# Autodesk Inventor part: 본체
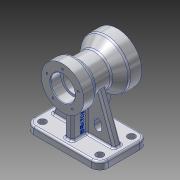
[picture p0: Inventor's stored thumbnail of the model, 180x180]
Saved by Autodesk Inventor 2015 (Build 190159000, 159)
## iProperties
Created: 2015-08
Part Number: 본체
Material: Aluminum 6061
Document SubType Name: Modeling
Designer: 601
Density: 2.7 g/cm^3
Appearance: Aluminum - Flat
Author: 601
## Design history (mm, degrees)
sketch "Sketch3"
  geometry: L1 (20, -5.906)-(20, -22.906); L2 (20, -22.906)-(16, -22.906); L3 (16, -22.906)-(16, -72.906); L4 (0, 0)-(0, -90); L5 (26, -95.906)-(26, -75.906); L6 (35, -5.906)-(35, -25.906); L7 (26, -95.906)-(40, -95.906); L8 (40, -95.906)-(40, -75.906); L9 (26.173, -31.002)-(35, -25.906); L10 (26.173, -59.428)-(40, -75.906); L11 (20, -17.072)-(20, -22.906); L12 (26.173, -31.002)-(26.173, -59.428); L13 (35, -5.906)-(20, -5.906); L14 (26, -75.906)-(19, -75.906); L15 (19, -75.906)-(19, -72.906); L16 (19, -72.906)-(16, -72.906)
  constraints: 32 end point, 7 vertical, 4 horizontal, 3 perpendicular
  dimensions: "d31" = 17 distance of L1.start L1.end; "d32" = 20 distance from line of L4.start L1; "d36" = 90 distance of L4.start L4.end; "d38" = 26 distance between parallel lines of L4 L5; "d39" = 20 distance of L6.start L6.end; "d40" = 35 distance between parallel lines of L4 L6; "d45" = 20 distance of L7.end L8.end; "d46" = 40 distance from line of L4 L7.end; "d132" = 90 distance between parallel lines of L7 L13; "d133" = 60 deg angle of L12 L9; "d134" = 40 deg angle of L12 L10; "d135" = 7 distance of L5.end L14.end; "d138" = 16 distance between parallel lines of L4 L3; "d139" = 50 distance between parallel lines of L2 L16; "d140" = 26.17342 distance between parallel lines of L4 L12
revolve "Revolution2" sketch "Sketch3" stored, may be unused: angle "d50" = 90 deg
workplane "Work Plane2"
sketch "Sketch7"
  geometry: L1 (-47, -85.906)-(47, -85.906); L2 (61, -71.906)-(61, -19.906); L3 (47, -5.906)-(-47, -5.906); L4 (-61, -19.906)-(-61, -71.906); C1 r 6 at (47, -71.906); C2 r 6 at (47, -19.906); C3 r 6 at (-47, -71.906); C4 r 6 at (-47, -19.906); A1 r 14 centre (-47, -19.906) between (-47, -5.906) and (-61, -19.906); A2 r 14 centre (47, -19.906) between (61, -19.906) and (47, -5.906); A3 r 14 centre (47, -71.906) between (47, -85.906) and (61, -71.906); A4 r 14 centre (-47, -71.906) between (-61, -71.906) and (-47, -85.906); 6 further points; 1 other entity
  constraints: 8 centre point, 8 end point, 8 point on circle, 8 tangent, 6 point on line, 5 equal radius, 2 horizontal alignment, 2 parallel, 1 coincident, 1 horizontal, 1 perpendicular, 1 vertical, 3 other
  dimensions: "d76" = 122 distance of point (-61, -5.906) point (61, -5.906); "d77" = 80 distance of point (61, -5.906) point (61, -85.906); "d78" = 80 dimension on L1; "d79" = 61 distance from line of point (0, 0) L4; "d80" = 14 radius of A1; "d81" = 12 diameter of C1; "d84" = 52 distance of C1.centre C2.centre; "d87" = 94 distance of C1.centre C3.centre
extrude "Extrusion2" join sketch "Sketch7" distance "d90" = 12; taper "d91" = 0 deg
workplane "Work Plane4"
sketch "Sketch8"
  geometry: L1 (108, 0)-(108, 12) reference; L2 (-14, 0)-(-14, 12) reference; L3 (0, 12)-(94, 12) reference; L4 (72.193, 82.904)-(98, 12); L5 (21.807, 82.904)-(-4, 12); L6 (-4, 12)-(98, 12); L7 (65, 30)-(65, 36); L8 (77, 30)-(77, 36); L9 (47, 90)-(47, 12); L10 (17.016, 36.433)-(17.016, 30); L11 (28.984, 36.433)-(28.984, 29.389); A1 r 26.173 centre (47, 90) between (72.193, 82.904) and (21.807, 82.904) reference; A2 r 26.173 centre (47, 90) between (21.807, 82.904) and (72.193, 82.904); A3 r 6 centre (71, 36) between (77, 36) and (65, 36); A4 r 6 centre (71, 30) between (65, 30) and (77, 30); A5 r 6 centre (23, 36) between (28.984, 35.567) and (17.016, 35.567); A6 r 6 centre (23.016, 30) between (17.016, 30) and (28.984, 30.611); 1 further point
  constraints: 18 point on circle, 16 end point, 6 point on line, 5 centre point, 3 tangent, 3 vertical, 1 concentric, 1 horizontal, 1 midpoint
  dimensions: "d93" = 10 distance from line of L1 L4.end; "d94" = 70 deg angle of L3 L4; "d95" = 10 horizontal distance of L2.start L5.end; "d96" = 70 deg angle of L3 L5; "d97" = 12 diameter of A3; "d100" = 12 diameter of A4; "d101" = 6 distance of A4.centre A3.centre; "d102" = 18 distance from line of L3 A4.centre; "d103" = 94 distance of L3.start L3.end (derived); "d104" = 23 horizontal distance of L3.end A4.centre; "d105" = 24 distance from line of L3 A3.centre; "d120" = 12 diameter of A5; "d123" = 48 distance of A3.centre A5.centre; "d124" = 24 distance from line of L3 A5.centre
extrude "Extrusion3" join sketch "Sketch8" stored distance "d106" = 12; taper "d107" = 0 deg
sketch "Sketch12"
  geometry: 6 further points
  constraints: 6 other
  dimensions: "d131" = 27 distance of point (0, 0) point (0, 27); "d141" = 0 horizontal distance of point (0, 0) point (0, 27); "d144" = 360 deg dimension on point (0, 0) point (0, 27) (derived)
hole "Hole1" sketch "Sketch12" at (0, 27), (-25.679, 8.343), (-15.87, -21.843), (15.87, -21.843), (25.679, 8.343) diameter "d146" = 3.242; stored, may be unused: countersink angle "d150" = 90 deg, drill point angle "d152" = 118 deg; dims "d147" = 10, "d148" = 4, "d149" = 2, "d151" = 13
fillet "Fillet1" dims "d166" = 5
sketch "Sketch13"
  geometry: 6 further points
  constraints: 6 other
  dimensions: "d153" = 33 distance of point (0, 33) point (0, 0); "d154" = 0 horizontal distance of point (0, 0) point (0, 33); "d157" = 360 deg dimension on point (0, 0) point (0, 33) (derived)
hole "Hole2" sketch "Sketch13" at (0, 33), (-31.385, 10.198), (-19.397, -26.698), (19.397, -26.698), (31.385, 10.198) diameter "d159" = 3.242; stored, may be unused: countersink angle "d163" = 90 deg, drill point angle "d165" = 118 deg; dims "d160" = 10, "d161" = 4, "d162" = 2, "d164" = 13
sketch "Sketch16"
  geometry: L1 (-90, -5.906)-(-78, -5.906) reference; L2 (-78, -19.906)-(-78, -5.906) reference; L3 (-78, -19.906)-(-78, -71.906) reference; L4 (-78, -85.906)-(-78, -71.906) reference; L5 (-90, -85.906)-(-78, -85.906) reference; L6 (-40, -77.726)-(-40, -95.906) reference; L7 (-27.343, -60.822)-(-38.83, -74.512) reference; L8 (-26.173, -33.889)-(-26.173, -57.608) reference; L9 (-32.5, -27.349)-(-28.673, -29.559) reference; L10 (-35, -5.906)-(-35, -23.019) reference; L11 (-35, -15.906)-(-78, -15.906); L12 (-40, -82.606)-(-78, -75.906); A1 r 5 centre (-35, -77.726) between (-38.83, -74.512) and (-40, -77.726) reference; A2 r 5 centre (-31.173, -57.608) between (-27.343, -60.822) and (-26.173, -57.608) reference; A3 r 5 centre (-31.173, -33.889) between (-26.173, -33.889) and (-28.673, -29.559) reference; A4 r 5 centre (-30, -23.019) between (-35, -23.019) and (-32.5, -27.349) reference; 1 further point
  constraints: 4 end point, 4 point on line, 1 horizontal
  dimensions: "d173" = 10 distance between parallel lines of L1 L11; "d174" = 10 distance of L4.start L12.end; "d175" = 80 deg angle of L4 L12
extrude "Extrusion6" join sketch "Sketch16" stored distance "d176" = 12; taper "d177" = 0 deg
fillet "Fillet3" dims "d179" = 3
sketch "Sketch17"
  geometry: L1 (15.906, -35)-(15.906, -75) reference; L2 (8.906, -78)-(19.906, -78) reference; L3 (28.762, -74.872)-(28.762, -33.393); L4 (28.762, -33.393)-(34.766, -33.393); L5 (34.766, -33.393)-(34.766, -74.872); L6 (34.766, -74.872)-(28.762, -74.872); 2 further points
  constraints: 2 other
  dimensions: "d180" = 16 distance from line of L1 point (31.906, -54); "d181" = 24 distance from line of L2 point (31.906, -54)
emboss "Emboss1" sketch "Sketch17" dims "d31" = 17, "d32" = 20, "d36" = 90, "d38" = 26, "d39" = 20, "d40" = 35, "d45" = 20, "d46" = 40, "d76" = 122, "d77" = 80, "d78" = 80, "d79" = 61, "d80" = 14, "d81" = 12, "d84" = 52, "d87" = 94, "d132" = 90, "d133" = 60 deg, "d134" = 40 deg, "d135" = 7, "d138" = 16, "d139" = 50, "d140" = 26.17342, "d182" = 0.5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
chamfer "Chamfer1" distance "d184" = 1; stored, may be unused: second distance "d185" = 2, angle "d186" = 45 deg
chamfer "Chamfer2" distance "d187" = 1; stored, may be unused: second distance "d188" = 2, angle "d189" = 45 deg
body "Solid2"
other parameters: "d41" = 26, "d48" = 60 deg, "d49" = 40 deg
